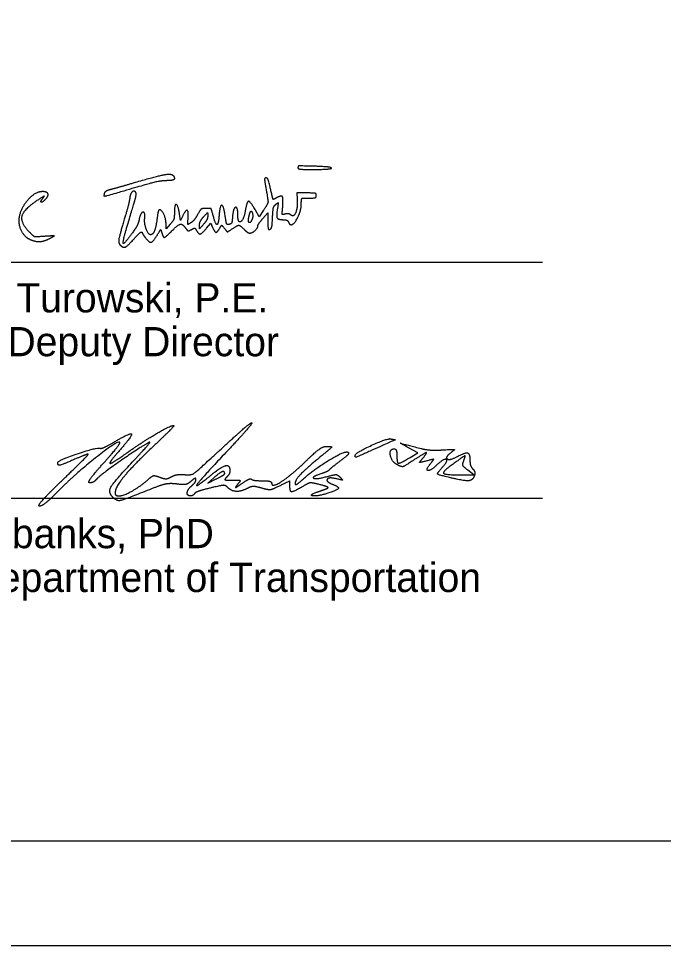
# Model space of a CAD drawing. Extents: x 0 to 34, y 0 to 22.
# Drawn here: x 25.517 to 28.607, y 0 to 4.44 of the extents above; entities that cross this region are included whole.
import ezdxf

# ---------------------------------------------------------------- set-up
doc = ezdxf.new("R2010")
doc.units = 0
for name, color, linetype in [('SH_Border', 7, 'Continuous'), ('SH_Cut_Line', 7, 'Continuous'), ('SH_Data', 7, 'Continuous'), ('SH_Text', 7, 'Continuous')]:
    doc.layers.add(name, color=color, linetype=linetype)

msp = doc.modelspace()

# ---------------------------------------------------------------- linework, layer by layer
at = {"layer": 'SH_Border'}
msp.add_lwpolyline([(1.5, 21.5), (33.5, 21.5), (33.5, 0.5), (1.5, 0.5)], close=True, dxfattribs=at)
at = {"layer": 'SH_Cut_Line'}
msp.add_lwpolyline([(0, 0), (34, 0), (34, 22), (0, 22)], close=True, dxfattribs=at)
at = {"layer": 'SH_Data'}
for p, q in [((24.5279, 3.2725), (28.0279, 3.2725)), ((24.5279, 2.1431), (28.0279, 2.1431))]:
    msp.add_line(p, q, dxfattribs=at)
at = {"layer": 'SH_Text'}
for p, q in [((25.9287, 3.601), (25.9287, 3.601)), ((25.5689, 3.3826), (25.5689, 3.3826)), ((27.1295, 2.3473), (27.1295, 2.3473)), ((25.7273, 2.2293), (25.7273, 2.2293)), ((26.5045, 2.2603), (26.5045, 2.2603)), ((27.582, 2.2411), (27.582, 2.2411))]:
    msp.add_line(p, q, dxfattribs=at)
for points in [[(26.8966, 3.6046), (26.8497, 3.6046), (26.8519, 3.5745)], [(26.6905, 3.5216), (26.6698, 3.4905), (26.6524, 3.5215)], [(26.6875, 3.4818), (26.7115, 3.5092), (26.7115, 3.4682)], [(26.3033, 3.4948), (26.2923, 3.4726), (26.2879, 3.504)], [(26.2437, 3.455), (26.224, 3.4326), (26.2237, 3.455)], [(26.4178, 3.436), (26.4375, 3.4594), (26.4463, 3.44)], [(27.3933, 2.3377), (27.4297, 2.3592), (27.3889, 2.3822)], [(27.642, 2.2542), (27.6982, 2.2543), (27.6695, 2.2764)], [(26.4527, 2.2406), (26.4232, 2.215), (26.4638, 2.2347)]]:
    msp.add_lwpolyline(points, dxfattribs=at)
for points in [[(26.9304, 3.7327), (26.8636, 3.7344), (26.8555, 3.7336), (26.8555, 3.7246)], [(26.9335, 3.7171), (27.0179, 3.7177), (27.0154, 3.7304), (26.9304, 3.7327)], [(26.0677, 3.6531), (26.1931, 3.6904), (26.2635, 3.6978), (26.2635, 3.6737)], [(26.8555, 3.7246), (26.8555, 3.7198), (26.8865, 3.7168), (26.9335, 3.7171)], [(26.2253, 3.6635), (26.1933, 3.6625), (26.1405, 3.649), (25.9407, 3.5906)], [(25.9595, 3.6224), (25.9749, 3.6262), (26.0236, 3.64), (26.0677, 3.6531)], [(26.2635, 3.6737), (26.2635, 3.6683), (26.2477, 3.6641), (26.2253, 3.6635)], [(26.6995, 3.6426), (26.7128, 3.5677), (26.7117, 3.5538), (26.6905, 3.5216)], [(26.7022, 3.6766), (26.6963, 3.6766), (26.6954, 3.6655), (26.6995, 3.6426)], [(26.7309, 3.5944), (26.7165, 3.6582), (26.7101, 3.6766), (26.7022, 3.6766)], [(25.5197, 3.4703), (25.5201, 3.5193), (25.5945, 3.6126), (25.6332, 3.6126)], [(25.6332, 3.6126), (25.6521, 3.6126), (25.6602, 3.592), (25.6474, 3.5765)], [(25.9407, 3.5906), (25.9295, 3.5874), (25.9266, 3.5899), (25.9287, 3.601)], [(25.9287, 3.601), (25.9304, 3.61), (25.9422, 3.6182), (25.9595, 3.6224)], [(26.039, 3.4508), (26.0736, 3.5663), (26.0827, 3.604), (26.0773, 3.6095)], [(26.0773, 3.6095), (26.0685, 3.6182), (26.0512, 3.5992), (26.0495, 3.579)], [(26.9435, 3.5926), (26.9435, 3.6019), (26.9329, 3.6046), (26.8966, 3.6046)], [(25.6195, 3.5772), (25.5442, 3.5296), (25.5228, 3.4641), (25.5678, 3.419)], [(25.6325, 3.5785), (25.6421, 3.5906), (25.6405, 3.5904), (25.6195, 3.5772)], [(25.6474, 3.5765), (25.6335, 3.5597), (25.6192, 3.5616), (25.6325, 3.5785)], [(26.0495, 3.579), (26.0487, 3.5687), (26.0371, 3.5236), (26.0237, 3.4787)], [(26.6524, 3.5215), (26.629, 3.5633), (26.6111, 3.5659), (26.605, 3.5283)], [(26.7525, 3.5812), (26.7378, 3.5733), (26.7353, 3.5748), (26.7309, 3.5944)], [(26.7492, 3.5499), (26.7609, 3.5595), (26.7616, 3.5575), (26.7571, 3.5291)], [(26.7823, 3.5369), (26.7857, 3.5805), (26.7766, 3.5941), (26.7525, 3.5812)], [(26.8519, 3.5745), (26.8547, 3.5345), (26.8354, 3.4874), (26.8211, 3.4993)], [(26.8715, 3.5513), (26.8715, 3.5674), (26.8742, 3.5802), (26.8775, 3.5797)], [(26.8775, 3.5797), (26.8808, 3.5791), (26.897, 3.5791), (26.9135, 3.5797)], [(26.9135, 3.5797), (26.9344, 3.5803), (26.9435, 3.5842), (26.9435, 3.5926)], [(26.1212, 3.4829), (26.1245, 3.5148), (26.1015, 3.5111), (26.0949, 3.4788)], [(26.1924, 3.5246), (26.1887, 3.5246), (26.1837, 3.5073), (26.1812, 3.4862)], [(26.2237, 3.455), (26.2235, 3.4794), (26.2031, 3.5246), (26.1924, 3.5246)], [(26.2635, 3.5097), (26.2635, 3.4869), (26.2578, 3.471), (26.2437, 3.455)], [(26.2879, 3.504), (26.2818, 3.5475), (26.2635, 3.5518), (26.2635, 3.5097)], [(26.3291, 3.4814), (26.332, 3.5176), (26.3181, 3.5248), (26.3033, 3.4948)], [(26.4155, 3.5308), (26.3961, 3.5303), (26.3878, 3.5242), (26.3747, 3.5009)], [(26.4032, 3.4902), (26.4221, 3.5116), (26.423, 3.5118), (26.4232, 3.495)], [(26.4493, 3.496), (26.4407, 3.5285), (26.4377, 3.5315), (26.4155, 3.5308)], [(26.5075, 3.4922), (26.5005, 3.5432), (26.4815, 3.5477), (26.4779, 3.4992)], [(26.5675, 3.5006), (26.5675, 3.54), (26.5449, 3.5312), (26.5419, 3.4907)], [(26.605, 3.5283), (26.5969, 3.4786), (26.5675, 3.4569), (26.5675, 3.5006)], [(26.6205, 3.4906), (26.6234, 3.5027), (26.6269, 3.514), (26.6284, 3.5157)], [(26.6284, 3.5157), (26.634, 3.5223), (26.641, 3.4921), (26.6366, 3.4806)], [(26.7338, 3.4865), (26.7355, 3.5232), (26.7401, 3.5425), (26.7492, 3.5499)], [(26.7571, 3.5291), (26.7513, 3.493), (26.7608, 3.4766), (26.7876, 3.4766)], [(26.795, 3.5038), (26.7808, 3.5001), (26.7796, 3.5033), (26.7823, 3.5369)], [(26.8229, 3.4526), (26.8376, 3.4526), (26.8715, 3.5214), (26.8715, 3.5513)], [(25.5689, 3.3826), (25.5476, 3.3929), (25.5194, 3.4431), (25.5197, 3.4703)], [(26.0237, 3.4787), (25.9997, 3.3977), (25.9946, 3.3642), (26.0048, 3.3539)], [(26.0949, 3.4788), (26.092, 3.4646), (26.0839, 3.4448), (26.0769, 3.4348)], [(26.1498, 3.4046), (26.1386, 3.4046), (26.1187, 3.459), (26.1212, 3.4829)], [(26.1812, 3.4862), (26.1762, 3.4442), (26.161, 3.4046), (26.1498, 3.4046)], [(26.3425, 3.4618), (26.3277, 3.4526), (26.3269, 3.4539), (26.3291, 3.4814)], [(26.3747, 3.5009), (26.3657, 3.4848), (26.3512, 3.4673), (26.3425, 3.4618)], [(26.3837, 3.4502), (26.3836, 3.4598), (26.3924, 3.4778), (26.4032, 3.4902)], [(26.4232, 3.495), (26.4234, 3.4854), (26.4146, 3.4674), (26.4037, 3.455)], [(26.4779, 3.4992), (26.4746, 3.4541), (26.461, 3.4526), (26.4493, 3.496)], [(26.5263, 3.4542), (26.516, 3.4523), (26.5119, 3.4606), (26.5075, 3.4922)], [(26.5419, 3.4907), (26.5402, 3.4668), (26.5356, 3.456), (26.5263, 3.4542)], [(26.6366, 3.4806), (26.6283, 3.459), (26.6149, 3.4673), (26.6205, 3.4906)], [(26.6635, 3.4468), (26.6635, 3.451), (26.6743, 3.4668), (26.6875, 3.4818)], [(26.7115, 3.4682), (26.7115, 3.439), (26.7144, 3.4282), (26.7215, 3.4306)], [(26.7215, 3.4306), (26.7278, 3.4327), (26.7324, 3.4533), (26.7338, 3.4865)], [(26.7876, 3.4766), (26.7976, 3.4766), (26.8078, 3.4712), (26.8104, 3.4646)], [(26.8211, 3.4993), (26.8153, 3.504), (26.8036, 3.5061), (26.795, 3.5038)], [(26.8104, 3.4646), (26.8129, 3.458), (26.8185, 3.4526), (26.8229, 3.4526)], [(25.5678, 3.419), (25.5906, 3.3963), (25.5952, 3.3949), (25.6398, 3.3982)], [(26.0769, 3.4348), (26.0249, 3.3601), (26.0132, 3.365), (26.039, 3.4508)], [(26.1826, 3.4051), (26.197, 3.4287), (26.1982, 3.4292), (26.2032, 3.4134)], [(26.2032, 3.4134), (26.2106, 3.3902), (26.2208, 3.3923), (26.2518, 3.4233)], [(26.2518, 3.4233), (26.2818, 3.4533), (26.3025, 3.4571), (26.318, 3.4353)], [(26.318, 3.4353), (26.3265, 3.4233), (26.3315, 3.4222), (26.3451, 3.4295)], [(26.3451, 3.4295), (26.3585, 3.4367), (26.3633, 3.4359), (26.3691, 3.4255)], [(26.3691, 3.4255), (26.3798, 3.4063), (26.3957, 3.4098), (26.4178, 3.436)], [(26.4037, 3.455), (26.3849, 3.4336), (26.384, 3.4334), (26.3837, 3.4502)], [(26.4463, 3.44), (26.4569, 3.4167), (26.4681, 3.4153), (26.4808, 3.4358)], [(26.4808, 3.4358), (26.49, 3.4505), (26.4907, 3.4505), (26.5039, 3.4342)], [(26.5039, 3.4342), (26.5173, 3.4175), (26.5176, 3.4175), (26.5405, 3.4328)], [(26.5405, 3.4328), (26.5671, 3.4505), (26.5784, 3.4497), (26.5999, 3.4281)], [(26.5999, 3.4281), (26.6085, 3.4196), (26.6197, 3.4126), (26.6249, 3.4126)], [(26.6249, 3.4126), (26.6366, 3.4126), (26.6635, 3.4364), (26.6635, 3.4468)], [(25.6639, 3.3848), (25.6366, 3.3707), (25.5956, 3.3698), (25.5689, 3.3826)], [(25.6398, 3.3982), (25.666, 3.4001), (25.6875, 3.4006), (25.6875, 3.3993)], [(25.6875, 3.3993), (25.6875, 3.398), (25.6769, 3.3915), (25.6639, 3.3848)], [(26.0048, 3.3539), (26.0182, 3.3406), (26.0408, 3.3516), (26.0719, 3.3866)], [(26.0719, 3.3866), (26.0918, 3.4089), (26.1072, 3.4205), (26.1092, 3.4147)], [(26.1092, 3.4147), (26.1112, 3.4093), (26.1191, 3.397), (26.1269, 3.3874)], [(26.1269, 3.3874), (26.1444, 3.3657), (26.1621, 3.3713), (26.1826, 3.4051)], [(26.0326, 2.3574), (26.1131, 2.414), (26.2445, 2.4912), (26.2602, 2.4912)], [(26.2602, 2.4912), (26.265, 2.4912), (26.2237, 2.4486), (26.1684, 2.3965)], [(26.4869, 2.3778), (26.5619, 2.4469), (26.6279, 2.5035), (26.6336, 2.5036)], [(26.6336, 2.5036), (26.6394, 2.5037), (26.5873, 2.4435), (26.518, 2.3699)], [(25.9736, 2.4109), (26.0524, 2.457), (26.0646, 2.4438), (26.0054, 2.3765)], [(26.0017, 2.4106), (25.9921, 2.4203), (25.7824, 2.2533), (25.7045, 2.1741)], [(26.142, 2.4102), (26.0929, 2.3824), (25.9046, 2.2502), (25.8914, 2.2342)], [(25.908, 2.3817), (25.9136, 2.3798), (25.9431, 2.393), (25.9736, 2.4109)], [(25.9239, 2.3103), (25.9702, 2.362), (26.0052, 2.4072), (26.0017, 2.4106)], [(26.0768, 2.3313), (26.123, 2.3805), (26.1523, 2.416), (26.142, 2.4102)], [(27.1295, 2.3473), (27.1295, 2.3597), (27.2823, 2.43), (27.3012, 2.4263)], [(27.3012, 2.4263), (27.3219, 2.4223), (27.3226, 2.4227), (27.201, 2.3681)], [(27.3889, 2.3822), (27.3461, 2.4063), (27.3452, 2.4063), (27.4482, 2.3799)], [(25.7047, 2.3131), (25.7049, 2.3236), (25.8923, 2.3868), (25.908, 2.3817)], [(25.7273, 2.2293), (25.7983, 2.2977), (25.8537, 2.3537), (25.8502, 2.3537)], [(25.8502, 2.3537), (25.8468, 2.3537), (25.8178, 2.3425), (25.7857, 2.3287)], [(26.0054, 2.3765), (25.9774, 2.3447), (25.9545, 2.315), (25.9545, 2.3106)], [(25.9545, 2.3106), (25.9545, 2.3061), (25.9896, 2.3272), (26.0326, 2.3574)], [(26.1684, 2.3965), (26.0687, 2.3028), (25.9795, 2.1947), (25.9795, 2.1677)], [(26.3119, 2.2554), (26.3453, 2.2526), (26.3688, 2.269), (26.4869, 2.3778)], [(26.518, 2.3699), (26.3885, 2.2324), (26.3564, 2.1851), (26.4386, 2.2528)], [(26.8763, 2.2304), (26.93, 2.2792), (27.0769, 2.3692), (27.0938, 2.3635)], [(26.8951, 2.3215), (26.9403, 2.3653), (26.9774, 2.391), (26.9951, 2.3907)], [(26.9951, 2.3907), (27.0194, 2.3902), (27.0156, 2.3838), (26.967, 2.3438)], [(27.0938, 2.3635), (27.1022, 2.3607), (27.087, 2.342), (27.0599, 2.3218)], [(27.201, 2.3681), (27.1385, 2.34), (27.1295, 2.3373), (27.1295, 2.3473)], [(27.3305, 2.3032), (27.304, 2.3174), (27.293, 2.3787), (27.317, 2.3787)], [(27.317, 2.3787), (27.3238, 2.3787), (27.3295, 2.3647), (27.3295, 2.3475)], [(27.4529, 2.3329), (27.4773, 2.3625), (27.4615, 2.3587), (27.4052, 2.3215)], [(27.4482, 2.3799), (27.4688, 2.3747), (27.5138, 2.3719), (27.5482, 2.3738)], [(27.5482, 2.3738), (27.6031, 2.3769), (27.608, 2.3753), (27.5881, 2.3605)], [(27.5881, 2.3605), (27.5593, 2.339), (27.5822, 2.3226), (27.6159, 2.3407)], [(27.6159, 2.3407), (27.6561, 2.3622), (27.6795, 2.3564), (27.6795, 2.325)], [(25.7857, 2.3287), (25.7231, 2.3019), (25.7044, 2.2983), (25.7047, 2.3131)], [(25.8581, 2.2162), (25.8478, 2.2162), (25.8767, 2.2575), (25.9239, 2.3103)], [(25.9697, 2.1456), (25.9445, 2.1708), (25.9734, 2.221), (26.0768, 2.3313)], [(26.7295, 2.2147), (26.7295, 2.1919), (26.8248, 2.2533), (26.8951, 2.3215)], [(26.967, 2.3438), (26.8929, 2.2828), (26.842, 2.2293), (26.842, 2.2126)], [(27.0599, 2.3218), (27.0328, 2.3016), (27.0079, 2.2816), (27.0045, 2.2774)], [(27.3295, 2.3475), (27.3295, 2.3107), (27.3438, 2.3085), (27.3933, 2.3377)], [(27.4052, 2.3215), (27.3652, 2.295), (27.3519, 2.2917), (27.3305, 2.3032)], [(27.4723, 2.3212), (27.4392, 2.313), (27.4374, 2.3141), (27.4529, 2.3329)], [(27.4924, 2.3105), (27.507, 2.3281), (27.5047, 2.3293), (27.4723, 2.3212)], [(27.5211, 2.3017), (27.4892, 2.2717), (27.4661, 2.2788), (27.4924, 2.3105)], [(27.5462, 2.289), (27.5767, 2.3227), (27.5551, 2.3336), (27.5211, 2.3017)], [(27.6497, 2.3219), (27.6596, 2.3477), (27.6514, 2.3446), (27.5888, 2.299)], [(27.6695, 2.2764), (27.6491, 2.2921), (27.6434, 2.3053), (27.6497, 2.3219)], [(27.6795, 2.325), (27.6795, 2.3092), (27.6858, 2.2899), (27.6936, 2.2821)], [(26.4386, 2.2528), (26.487, 2.2927), (26.5295, 2.3031), (26.5295, 2.275)], [(26.5045, 2.2603), (26.5045, 2.2738), (26.4804, 2.2646), (26.4527, 2.2406)], [(26.5295, 2.275), (26.5295, 2.266), (26.5227, 2.252), (26.5145, 2.2437)], [(27.0045, 2.2774), (27.001, 2.2731), (26.9856, 2.2657), (26.9701, 2.2608)], [(27.582, 2.2411), (27.5272, 2.254), (27.5215, 2.2617), (27.5462, 2.289)], [(27.5888, 2.299), (27.5461, 2.268), (27.5626, 2.2541), (27.642, 2.2542)], [(27.6936, 2.2821), (27.7014, 2.2743), (27.7044, 2.2591), (27.7003, 2.2483)], [(25.617, 2.1044), (25.6067, 2.1046), (25.6563, 2.1608), (25.7273, 2.2293)], [(25.8914, 2.2342), (25.8831, 2.2243), (25.8682, 2.2162), (25.8581, 2.2162)], [(25.9975, 2.1537), (26.0192, 2.1537), (26.1006, 2.1989), (26.137, 2.2312)], [(26.137, 2.2312), (26.1573, 2.2493), (26.1701, 2.2519), (26.1939, 2.2429)], [(26.1939, 2.2429), (26.2141, 2.2352), (26.2329, 2.2359), (26.2489, 2.2449)], [(26.2489, 2.2449), (26.2623, 2.2525), (26.2906, 2.2572), (26.3119, 2.2554)], [(26.3444, 2.2247), (26.3287, 2.2105), (26.3075, 2.2061), (26.2749, 2.2103)], [(26.367, 2.2322), (26.367, 2.2393), (26.3568, 2.2359), (26.3444, 2.2247)], [(26.3482, 2.2037), (26.3585, 2.2123), (26.367, 2.2251), (26.367, 2.2322)], [(26.4638, 2.2347), (26.4862, 2.2455), (26.5045, 2.257), (26.5045, 2.2603)], [(26.5145, 2.2437), (26.5028, 2.2321), (26.5087, 2.2287), (26.541, 2.2287)], [(26.541, 2.2287), (26.5785, 2.2287), (26.5809, 2.2267), (26.5654, 2.2073)], [(26.5871, 2.2132), (26.6085, 2.2282), (26.6293, 2.2373), (26.6332, 2.2334)], [(26.6332, 2.2334), (26.6371, 2.2294), (26.6604, 2.2262), (26.6849, 2.2262)], [(26.6849, 2.2262), (26.7094, 2.2262), (26.7295, 2.2211), (26.7295, 2.2147)], [(26.817, 2.2022), (26.817, 2.2251), (26.8159, 2.2251), (26.7698, 2.2022)], [(26.842, 2.2126), (26.842, 2.2051), (26.8574, 2.2131), (26.8763, 2.2304)], [(26.9701, 2.2608), (26.9206, 2.2454), (26.9401, 2.2317), (26.9919, 2.2455)], [(26.9919, 2.2455), (27.0302, 2.2558), (27.0455, 2.2552), (27.0575, 2.2429)], [(27.0388, 2.2355), (27.0021, 2.2445), (26.9889, 2.2214), (27.0232, 2.2083)], [(27.0575, 2.2429), (27.0702, 2.23), (27.0666, 2.2286), (27.0388, 2.2355)], [(27.7003, 2.2483), (27.6922, 2.2272), (27.651, 2.2247), (27.582, 2.2411)], [(26.1693, 2.1931), (26.0233, 2.1354), (25.9882, 2.1271), (25.9697, 2.1456)], [(26.2749, 2.2103), (26.2457, 2.214), (26.2058, 2.2075), (26.1693, 2.1931)], [(26.3412, 2.1537), (26.3229, 2.1537), (26.3274, 2.1865), (26.3482, 2.2037)], [(26.4355, 2.1912), (26.3972, 2.182), (26.3629, 2.1698), (26.3594, 2.1641)], [(26.5199, 2.1933), (26.5088, 2.2045), (26.4887, 2.2039), (26.4355, 2.1912)], [(26.6162, 2.1908), (26.5854, 2.1744), (26.5376, 2.1756), (26.5199, 2.1933)], [(26.5654, 2.2073), (26.5533, 2.1923), (26.5598, 2.1941), (26.5871, 2.2132)], [(26.6807, 2.1909), (26.6538, 2.1986), (26.6307, 2.1986), (26.6162, 2.1908)], [(26.7698, 2.2022), (26.7324, 2.1837), (26.7138, 2.1814), (26.6807, 2.1909)], [(26.8789, 2.1991), (26.8339, 2.1725), (26.817, 2.1734), (26.817, 2.2022)], [(26.9621, 2.2072), (26.9233, 2.217), (26.9065, 2.2154), (26.8789, 2.1991)], [(26.9482, 2.1722), (26.962, 2.1771), (26.9817, 2.1842), (26.992, 2.188)], [(26.992, 2.188), (27.0034, 2.1921), (26.9917, 2.1996), (26.9621, 2.2072)], [(27.0232, 2.2083), (27.0538, 2.1965), (27.0449, 2.1816), (26.9981, 2.1662)], [(25.7045, 2.1741), (25.6667, 2.1356), (25.6273, 2.1042), (25.617, 2.1044)], [(25.9795, 2.1677), (25.9795, 2.16), (25.9876, 2.1537), (25.9975, 2.1537)], [(26.3594, 2.1641), (26.3559, 2.1584), (26.3477, 2.1537), (26.3412, 2.1537)], [(26.9981, 2.1662), (26.9515, 2.1508), (26.9042, 2.1565), (26.9482, 2.1722)]]:
    msp.add_open_spline(points, degree=2, dxfattribs=at)

# ---------------------------------------------------------------- texts
for s, p in [('Anthony C. Turowski, P.E.', (24.5279, 3.0325)), ('District       Deputy Director', (24.5279, 2.8225)), ('Jack Marchbanks, PhD', (24.5279, 1.9031)), ('Director, Department of Transportation', (24.5279, 1.6931))]:
    msp.add_text(s, height=0.14, dxfattribs=at).set_placement(p)

doc.saveas('drawing.dxf')
